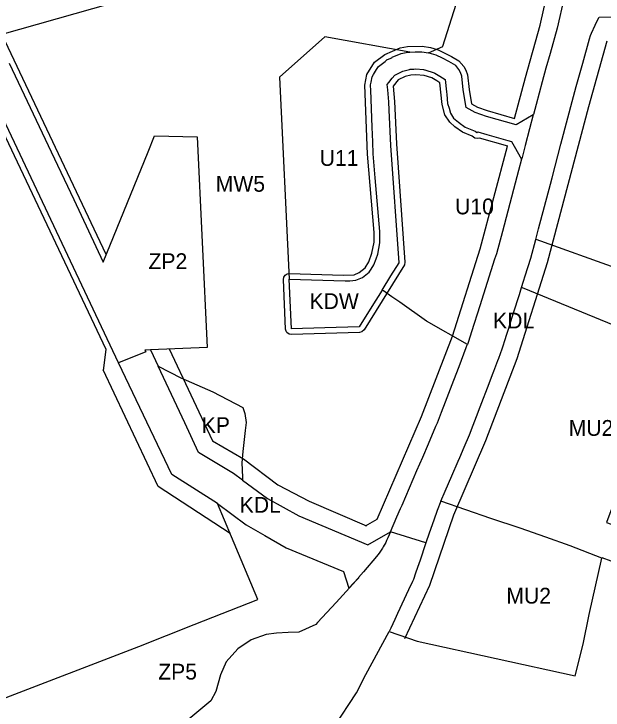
# Model space of a CAD drawing. Extents: x 7428080 to 7432143, y 5545880 to 5549217.
# Drawn here: x 7429133.6 to 7429340.3, y 5548240.2 to 5548484.5 of the extents above; entities that cross this region are included whole.
import ezdxf

# ---------------------------------------------------------------- set-up
doc = ezdxf.new("R2010")
doc.units = 0
for name, color, linetype in [('CZ_L_linie rozgraniczające tereny o różnym przeznaczeniu oraz różnych warunkach ich zabudowy i zagospodarowania', 7, 'Continuous'), ('CZ_L_maksymalne nieprzekraczalne linie zabudowy', 7, 'Continuous'), ('CZ_L_opisy_linie rozgraniczające tereny o różnym przeznaczeniu oraz różnych warunkach ich zabudowy i zagospodarowania', 7, 'Continuous')]:
    doc.layers.add(name, color=color, linetype=linetype)

msp = doc.modelspace()

# ---------------------------------------------------------------- linework, layer by layer
at = {"layer": 'CZ_L_linie rozgraniczające tereny o różnym przeznaczeniu oraz różnych warunkach ich zabudowy i zagospodarowania'}
for p, q in [((7429327.04, 5548492.22), (7429324.23, 5548479.58)), ((7429284.06, 5548473.2), (7429288.76, 5548487.94)), ((7429337.57, 5548480.59), (7429338.47, 5548482.58)), ((7429338.47, 5548482.58), (7429338.93, 5548483.39)), ((7429338.93, 5548483.39), (7429344.19, 5548483.46)), ((7429324.23, 5548479.58), (7429321.74, 5548470.69)), ((7429336.32, 5548477.77), (7429337.57, 5548480.59)), ((7429335.95, 5548476.94), (7429336.32, 5548477.77)), ((7429242.67, 5548476.47), (7429226.73, 5548462.3)), ((7429272.53, 5548471.15), (7429242.67, 5548476.47)), ((7429333.23, 5548467.22), (7429335.62, 5548475.77)), ((7429335.62, 5548475.77), (7429335.95, 5548476.94)), ((7429279.05, 5548470.85), (7429284.05, 5548473.14)), ((7429284.05, 5548473.14), (7429284.06, 5548473.2)), ((7429266.36, 5548469.34), (7429269.48, 5548470.67)), ((7429269.48, 5548470.67), (7429271.85, 5548471.11)), ((7429271.85, 5548471.11), (7429272.53, 5548471.15)), ((7429272.53, 5548471.15), (7429274.44, 5548471.26)), ((7429274.44, 5548471.26), (7429276.78, 5548471.26)), ((7429276.78, 5548471.26), (7429279.05, 5548470.85)), ((7429279.32, 5548470.8), (7429279.05, 5548470.85)), ((7429281.81, 5548470.09), (7429279.32, 5548470.8)), ((7429284.03, 5548468.98), (7429281.81, 5548470.09)), ((7429321.74, 5548470.69), (7429320.3, 5548465.51)), ((7429131.92, 5548467.27), (7429143.51, 5548442.76)), ((7429261.47, 5548466.08), (7429263.81, 5548467.86)), ((7429263.81, 5548467.86), (7429264.62, 5548468.48)), ((7429264.62, 5548468.48), (7429264.71, 5548468.55)), ((7429264.71, 5548468.55), (7429266.26, 5548469.1)), ((7429266.26, 5548469.1), (7429266.36, 5548469.34)), ((7429286.2, 5548467.83), (7429284.03, 5548468.98)), ((7429288.7, 5548466.37), (7429286.2, 5548467.83)), ((7429170.34, 5548362.1), (7429120.73, 5548466.86)), ((7429259.76, 5548463.31), (7429260.78, 5548464.97)), ((7429260.78, 5548464.97), (7429261.47, 5548466.08)), ((7429270.1, 5548464.43), (7429272.41, 5548465.06)), ((7429272.41, 5548465.06), (7429272.61, 5548465.08)), ((7429272.61, 5548465.08), (7429273.94, 5548465.17)), ((7429273.94, 5548465.17), (7429274.59, 5548465.21)), ((7429274.59, 5548465.21), (7429277.29, 5548464.98)), ((7429277.29, 5548464.98), (7429277.7, 5548464.94)), ((7429277.7, 5548464.94), (7429277.83, 5548464.93)), ((7429277.83, 5548464.93), (7429281.02, 5548463.89)), ((7429289.73, 5548465.04), (7429288.7, 5548466.37)), ((7429290.35, 5548464), (7429289.73, 5548465.04)), ((7429320.3, 5548465.51), (7429318.94, 5548460.65)), ((7429330.95, 5548459.05), (7429333.23, 5548467.22)), ((7429258.91, 5548460.56), (7429259.25, 5548462.49)), ((7429259.25, 5548462.49), (7429259.76, 5548463.31)), ((7429266.27, 5548462), (7429267.3, 5548463.08)), ((7429267.3, 5548463.08), (7429270.1, 5548464.43)), ((7429281.02, 5548463.89), (7429281.29, 5548463.74)), ((7429281.29, 5548463.74), (7429283.07, 5548462.73)), ((7429283.07, 5548462.73), (7429284.92, 5548461.52)), ((7429290.8, 5548462.65), (7429290.35, 5548464)), ((7429291.29, 5548457.88), (7429290.8, 5548462.65)), ((7429226.73, 5548462.3), (7429230.14, 5548391.41)), ((7429258.75, 5548459.65), (7429258.91, 5548460.56)), ((7429264.61, 5548459.71), (7429265.18, 5548460.49)), ((7429265.18, 5548460.49), (7429266.27, 5548462)), ((7429284.92, 5548461.52), (7429285.37, 5548457.16)), ((7429318.94, 5548460.65), (7429316.82, 5548452.76)), ((7429258.71, 5548459.44), (7429258.75, 5548459.65)), ((7429258.78, 5548457.8), (7429258.71, 5548459.44)), ((7429259.26, 5548444.81), (7429258.78, 5548457.8)), ((7429264.83, 5548457.88), (7429264.61, 5548459.71)), ((7429265.19, 5548453.7), (7429264.83, 5548457.88)), ((7429292.32, 5548451.68), (7429291.29, 5548457.88)), ((7429329.96, 5548455.51), (7429330.95, 5548459.05)), ((7429285.37, 5548457.16), (7429285.46, 5548456.29)), ((7429285.46, 5548456.29), (7429285.79, 5548453.09)), ((7429325.56, 5548438.86), (7429329.96, 5548455.51)), ((7429265.33, 5548450.72), (7429265.19, 5548453.7)), ((7429285.79, 5548453.09), (7429286.27, 5548451.45)), ((7429316.82, 5548452.76), (7429315.88, 5548449.21)), ((7429265.91, 5548438.4), (7429265.33, 5548450.72)), ((7429286.27, 5548451.45), (7429286.78, 5548449.71)), ((7429295.41, 5548449.95), (7429292.32, 5548451.68)), ((7429286.78, 5548449.71), (7429287.89, 5548447.96)), ((7429287.89, 5548447.96), (7429289.61, 5548446.5)), ((7429299.47, 5548448.55), (7429295.41, 5548449.95)), ((7429309.8, 5548445.6), (7429299.47, 5548448.55)), ((7429315.85, 5548449.08), (7429309.8, 5548445.6)), ((7429315.85, 5548449.08), (7429314.57, 5548444.24)), ((7429315.88, 5548449.21), (7429315.85, 5548449.08)), ((7429289.61, 5548446.5), (7429290.65, 5548445.75)), ((7429290.65, 5548445.75), (7429291.04, 5548445.47)), ((7429291.04, 5548445.47), (7429291.99, 5548444.79)), ((7429259.49, 5548439.66), (7429259.26, 5548444.81)), ((7429291.99, 5548444.79), (7429295.5, 5548443.33)), ((7429295.5, 5548443.33), (7429295.92, 5548443)), ((7429295.92, 5548443), (7429296.19, 5548442.79)), ((7429296.19, 5548442.79), (7429296.32, 5548443.04)), ((7429296.32, 5548443.04), (7429296.36, 5548443.12)), ((7429296.36, 5548443.12), (7429299.6, 5548442.24)), ((7429314.57, 5548444.24), (7429313, 5548438.29)), ((7429143.51, 5548442.76), (7429146.68, 5548436.06)), ((7429180.67, 5548436.17), (7429182.91, 5548441.72)), ((7429182.91, 5548441.72), (7429197.91, 5548441.33)), ((7429197.91, 5548441.33), (7429201.43, 5548367.39)), ((7429299.6, 5548442.24), (7429306.91, 5548440.13)), ((7429259.69, 5548435.44), (7429259.49, 5548439.66)), ((7429268.79, 5548397.21), (7429265.91, 5548438.4)), ((7429306.91, 5548440.13), (7429308.25, 5548439.74)), ((7429308.25, 5548439.74), (7429309.18, 5548438.09)), ((7429309.18, 5548438.09), (7429311.73, 5548433.51)), ((7429313, 5548438.29), (7429311.89, 5548434.1)), ((7429322.42, 5548426.98), (7429325.56, 5548438.86)), ((7429146.68, 5548436.06), (7429154.57, 5548419.39)), ((7429164.96, 5548397.41), (7429180.67, 5548436.17)), ((7429260.39, 5548427.04), (7429259.69, 5548435.44)), ((7429311.73, 5548433.51), (7429310.69, 5548429.58)), ((7429311.89, 5548434.1), (7429311.73, 5548433.51)), ((7429310.69, 5548429.58), (7429309.5, 5548425.07)), ((7429261.96, 5548408.13), (7429260.39, 5548427.04)), ((7429321.84, 5548424.8), (7429322.42, 5548426.98)), ((7429309.5, 5548425.07), (7429305.04, 5548408.18)), ((7429317.69, 5548409.08), (7429321.84, 5548424.8)), ((7429154.57, 5548419.39), (7429164.96, 5548397.41)), ((7429316.7, 5548405.36), (7429317.69, 5548409.08)), ((7429262.01, 5548404.13), (7429261.96, 5548408.13)), ((7429305.04, 5548408.18), (7429302.91, 5548400.33)), ((7429261.26, 5548400.2), (7429262.01, 5548404.13)), ((7429314.98, 5548398.84), (7429316.7, 5548405.36)), ((7429316.88, 5548405.29), (7429316.7, 5548405.36)), ((7429373.74, 5548384.85), (7429316.88, 5548405.29)), ((7429260.69, 5548398.57), (7429261.26, 5548400.2)), ((7429302.91, 5548400.33), (7429302.29, 5548398.4)), ((7429313.05, 5548392.63), (7429314.98, 5548398.84)), ((7429258.95, 5548394.9), (7429259.94, 5548396.41)), ((7429259.94, 5548396.41), (7429260.69, 5548398.57)), ((7429265.89, 5548392.55), (7429268.79, 5548397.21)), ((7429302.29, 5548398.4), (7429297.12, 5548382.09)), ((7429258.29, 5548393.89), (7429258.95, 5548394.9)), ((7429253.56, 5548391.02), (7429255.9, 5548392.06)), ((7429255.9, 5548392.06), (7429258.29, 5548393.89)), ((7429262.81, 5548387.59), (7429265.89, 5548392.55)), ((7429312.46, 5548390.75), (7429313.05, 5548392.63)), ((7429230.14, 5548391.37), (7429230.14, 5548391.41)), ((7429230.14, 5548391.41), (7429249.81, 5548390.78)), ((7429230.94, 5548374.03), (7429230.14, 5548391.37)), ((7429249.81, 5548390.78), (7429251.51, 5548390.89)), ((7429251.51, 5548390.89), (7429253.56, 5548391.02)), ((7429311.75, 5548388.53), (7429312.46, 5548390.75)), ((7429262.81, 5548387.59), (7429259.24, 5548381.85)), ((7429263.23, 5548387.29), (7429262.81, 5548387.59)), ((7429266.19, 5548385.23), (7429263.23, 5548387.29)), ((7429310.98, 5548386.09), (7429311.75, 5548388.53)), ((7429268.98, 5548383.3), (7429266.19, 5548385.23)), ((7429308.92, 5548379.6), (7429310.98, 5548386.09)), ((7429259.24, 5548381.85), (7429254.8, 5548374.71)), ((7429278.43, 5548376.72), (7429268.98, 5548383.3)), ((7429297.12, 5548382.09), (7429294.21, 5548372.93)), ((7429307.11, 5548373.88), (7429308.92, 5548379.6)), ((7429254.76, 5548374.65), (7429242.74, 5548374.29)), ((7429254.8, 5548374.71), (7429254.76, 5548374.65)), ((7429292.73, 5548368.45), (7429278.43, 5548376.72)), ((7429230.95, 5548373.94), (7429230.94, 5548374.03)), ((7429242.74, 5548374.29), (7429230.95, 5548373.94)), ((7429294.21, 5548372.93), (7429293.12, 5548369.48)), ((7429306.16, 5548371), (7429307.11, 5548373.88)), ((7429293.12, 5548369.48), (7429292.73, 5548368.45)), ((7429304.91, 5548366.96), (7429306.18, 5548370.99)), ((7429306.18, 5548370.99), (7429306.16, 5548371)), ((7429201.43, 5548367.39), (7429181.52, 5548366.62)), ((7429289.8, 5548360.81), (7429292.34, 5548367.43)), ((7429292.34, 5548367.43), (7429292.7, 5548368.39)), ((7429292.7, 5548368.39), (7429292.73, 5548368.45)), ((7429179.88, 5548365.87), (7429170.34, 5548362.1)), ((7429181.52, 5548366.62), (7429179.56, 5548366.55)), ((7429179.56, 5548366.55), (7429179.88, 5548365.87)), ((7429181.52, 5548366.62), (7429184.19, 5548360.91)), ((7429303.74, 5548363.7), (7429304.39, 5548365.34)), ((7429304.39, 5548365.34), (7429304.91, 5548366.96)), ((7429302.02, 5548359.16), (7429303.43, 5548362.83)), ((7429303.43, 5548362.83), (7429303.45, 5548362.83)), ((7429303.45, 5548362.83), (7429303.74, 5548363.7)), ((7429188.95, 5548322.79), (7429170.34, 5548362.1)), ((7429193.53, 5548340.93), (7429184.19, 5548360.91)), ((7429184.19, 5548360.91), (7429192.19, 5548356.8)), ((7429287.95, 5548355.97), (7429289.8, 5548360.81)), ((7429300.37, 5548354.85), (7429301.55, 5548357.93)), ((7429301.55, 5548357.93), (7429302.02, 5548359.16)), ((7429192.19, 5548356.8), (7429203.4, 5548351.91)), ((7429285.04, 5548348.39), (7429287.95, 5548355.97)), ((7429297.23, 5548346.65), (7429300.37, 5548354.85)), ((7429203.4, 5548351.91), (7429213.93, 5548346.41)), ((7429283.58, 5548344.7), (7429285.04, 5548348.39)), ((7429213.93, 5548346.41), (7429214.66, 5548344.23)), ((7429295.9, 5548343.19), (7429297.23, 5548346.65)), ((7429214.66, 5548344.23), (7429215.06, 5548341.16)), ((7429282.22, 5548341.02), (7429283.58, 5548344.7)), ((7429294.72, 5548340.11), (7429295.9, 5548343.19)), ((7429198.42, 5548330.59), (7429193.53, 5548340.93)), ((7429215.06, 5548341.16), (7429214.74, 5548338.24)), ((7429281.7, 5548339.8), (7429282.22, 5548341.02)), ((7429214.74, 5548338.24), (7429213.93, 5548330.96)), ((7429279.04, 5548333.63), (7429281.7, 5548339.8)), ((7429293.46, 5548336.83), (7429294.72, 5548340.11)), ((7429291.61, 5548332.49), (7429293.46, 5548336.83)), ((7429277.03, 5548328.97), (7429279.04, 5548333.63)), ((7429210.7, 5548323.15), (7429198.42, 5548330.59)), ((7429213.93, 5548330.96), (7429213.6, 5548326.9)), ((7429290.04, 5548328.84), (7429291.61, 5548332.49)), ((7429275, 5548324.26), (7429277.03, 5548328.97)), ((7429289.48, 5548327.53), (7429290.04, 5548328.84)), ((7429213.6, 5548326.9), (7429213.83, 5548321.88)), ((7429287.24, 5548322.33), (7429289.48, 5548327.53)), ((7429213.78, 5548320.89), (7429210.7, 5548323.15)), ((7429269.79, 5548312.14), (7429275, 5548324.26)), ((7429205.02, 5548312.72), (7429188.95, 5548322.79)), ((7429213.83, 5548321.88), (7429213.78, 5548320.89)), ((7429213.78, 5548320.89), (7429222.6, 5548314.4)), ((7429284.94, 5548316.99), (7429287.24, 5548322.33)), ((7429283.45, 5548313.44), (7429284.94, 5548316.99)), ((7429222.6, 5548314.4), (7429233.58, 5548308.32)), ((7429283.45, 5548313.44), (7429282.1, 5548310.25)), ((7429300.98, 5548307.36), (7429283.45, 5548313.44)), ((7429209.95, 5548300.95), (7429205.02, 5548312.72)), ((7429205.02, 5548312.72), (7429215.04, 5548305.17)), ((7429268.01, 5548308.02), (7429269.28, 5548310.97)), ((7429269.28, 5548310.97), (7429269.79, 5548312.14)), ((7429282.1, 5548310.25), (7429280.92, 5548306.79)), ((7429233.58, 5548308.32), (7429257.79, 5548298.16)), ((7429265.71, 5548302.68), (7429268.01, 5548308.02)), ((7429280.92, 5548306.79), (7429279.36, 5548302.24)), ((7429311.27, 5548303.99), (7429300.98, 5548307.36)), ((7429215.04, 5548305.17), (7429221.69, 5548301.41)), ((7429320.2, 5548300.85), (7429311.27, 5548303.99)), ((7429221.69, 5548301.41), (7429229.11, 5548297.07)), ((7429257.79, 5548298.16), (7429265.71, 5548302.68)), ((7429265.71, 5548302.68), (7429264.81, 5548300.58)), ((7429278.18, 5548298.81), (7429265.71, 5548302.68)), ((7429279.36, 5548302.24), (7429278.18, 5548298.81)), ((7429219.15, 5548278.95), (7429209.95, 5548300.95)), ((7429264.06, 5548299), (7429263.18, 5548297.45)), ((7429264.38, 5548299.67), (7429264.06, 5548299)), ((7429264.81, 5548300.58), (7429264.38, 5548299.67)), ((7429278.18, 5548298.81), (7429276.01, 5548292.48)), ((7429328.77, 5548297.85), (7429320.2, 5548300.85)), ((7429229.11, 5548297.07), (7429249.29, 5548288.8)), ((7429262.93, 5548297), (7429261.79, 5548295.18)), ((7429263.16, 5548297.42), (7429262.93, 5548297)), ((7429263.18, 5548297.45), (7429263.16, 5548297.42)), ((7429339.94, 5548293.49), (7429328.77, 5548297.85)), ((7429260.87, 5548294.09), (7429256.3, 5548288.71)), ((7429261.79, 5548295.18), (7429260.87, 5548294.09)), ((7429275.8, 5548291.87), (7429274.55, 5548288.21)), ((7429276.01, 5548292.48), (7429275.8, 5548291.87)), ((7429335.47, 5548273.67), (7429339.93, 5548293.42)), ((7429339.93, 5548293.42), (7429339.94, 5548293.49)), ((7429249.29, 5548288.8), (7429249.28, 5548288.79)), ((7429249.28, 5548288.79), (7429251.17, 5548282.96)), ((7429251.17, 5548282.96), (7429254.47, 5548286.56)), ((7429254.46, 5548286.46), (7429253.66, 5548285.6)), ((7429254.47, 5548286.56), (7429254.46, 5548286.46)), ((7429254.54, 5548286.65), (7429254.47, 5548286.56)), ((7429256.3, 5548288.71), (7429254.54, 5548286.65)), ((7429274.55, 5548288.21), (7429273.79, 5548285.99)), ((7429253.66, 5548285.6), (7429246.64, 5548277.96)), ((7429273.44, 5548285.25), (7429272.08, 5548282.34)), ((7429273.79, 5548285.99), (7429273.44, 5548285.25)), ((7429272.08, 5548282.34), (7429268.23, 5548274.09)), ((7429196.87, 5548270.18), (7429219.15, 5548278.95)), ((7429246.64, 5548277.96), (7429240.18, 5548270.95)), ((7429267.23, 5548271.95), (7429265.83, 5548268.95)), ((7429268.23, 5548274.09), (7429267.23, 5548271.95)), ((7429333.33, 5548263.33), (7429335.47, 5548273.67)), ((7429177.42, 5548262.52), (7429196.87, 5548270.18)), ((7429239.53, 5548270.24), (7429233.62, 5548267.48)), ((7429240.18, 5548270.95), (7429239.53, 5548270.24)), ((7429225.79, 5548267.17), (7429222.05, 5548266.67)), ((7429229.87, 5548267.33), (7429225.79, 5548267.17)), ((7429233.62, 5548267.48), (7429229.87, 5548267.33)), ((7429257.04, 5548252.68), (7429265.27, 5548267.75)), ((7429265.83, 5548268.95), (7429265.27, 5548267.75)), ((7429265.27, 5548267.75), (7429275.08, 5548264.33)), ((7429216.84, 5548264.76), (7429212.19, 5548261.67)), ((7429222.05, 5548266.67), (7429216.84, 5548264.76)), ((7429124.64, 5548242.13), (7429177.42, 5548262.52)), ((7429275.08, 5548264.33), (7429330.57, 5548252.2)), ((7429330.57, 5548252.2), (7429333.33, 5548263.33)), ((7429212.19, 5548261.67), (7429208.11, 5548257.07)), ((7429208.11, 5548257.07), (7429206.08, 5548252.55)), ((7429206.08, 5548252.55), (7429204.44, 5548246.68)), ((7429253.81, 5548246.23), (7429257.04, 5548252.68)), ((7429204.44, 5548246.68), (7429202.7, 5548243.37)), ((7429240.31, 5548225.7), (7429253.81, 5548246.23)), ((7429202.7, 5548243.37), (7429192.13, 5548234.58))]:
    msp.add_line(p, q, dxfattribs=at)
for points in [[(7429311.75, 5548388.53), (7429311.92, 5548388.46), (7429364.74, 5548366.81), (7429364.8, 5548366.69)], [(7429364.8, 5548366.68), (7429364.56, 5548366.78), (7429353.17, 5548336.76), (7429353.18, 5548336.53), (7429353.02, 5548336.6), (7429347.38, 5548321.65), (7429344.45, 5548313.86), (7429341.48, 5548305.99), (7429347.09, 5548303.97), (7429347.05, 5548303.86), (7429347.01, 5548303.73), (7429343.2, 5548292.46), (7429343.19, 5548292.43), (7429343.19, 5548292.42), (7429343.19, 5548292.42), (7429339.97, 5548293.62), (7429339.94, 5548293.49)]]:
    msp.add_lwpolyline(points, dxfattribs=at)
at = {"layer": 'CZ_L_maksymalne nieprzekraczalne linie zabudowy'}
for points in [[(7429231.04, 5548506.18), (7429129.39, 5548477.29), (7429165.81, 5548400.16)], [(7429306.91, 5548438.05), (7429296.92, 5548440.9), (7429296.13, 5548440.79), (7429295.38, 5548440.96), (7429294.35, 5548441.64), (7429290.95, 5548443.08), (7429288.35, 5548444.94), (7429286.53, 5548446.5), (7429284.86, 5548449.13), (7429283.82, 5548452.75), (7429283.02, 5548460.37), (7429282.04, 5548461.01), (7429280.24, 5548462.04), (7429277.5, 5548462.94), (7429274.67, 5548463.2), (7429272.82, 5548463.09), (7429270.9, 5548462.58), (7429268.47, 5548461.41), (7429266.69, 5548459.14), (7429267.19, 5548453.8), (7429267.89, 5548438.9), (7429270.79, 5548397.35), (7429270.62, 5548396.4), (7429256.45, 5548373.59), (7429255.72, 5548372.89), (7429254.84, 5548372.65), (7429231.01, 5548371.94), (7429230.13, 5548372.12), (7429229.41, 5548372.66), (7429229.08, 5548373.22), (7429228.95, 5548373.83), (7429228.14, 5548391.33), (7429228.26, 5548392.11), (7429228.76, 5548392.86), (7429229.42, 5548393.28), (7429230.18, 5548393.41), (7429249.21, 5548392.8), (7429252.96, 5548392.98), (7429254.79, 5548393.76), (7429256.87, 5548395.37), (7429258.18, 5548397.45), (7429259.24, 5548400.5), (7429260, 5548404.42), (7429259.97, 5548407.75), (7429257.69, 5548435.32), (7429256.71, 5548459.49), (7429257.42, 5548463.3), (7429260.1, 5548467.54), (7429263.76, 5548470.31), (7429269.11, 5548472.63), (7429271.72, 5548473.11), (7429276.84, 5548473.26), (7429279.75, 5548472.75), (7429282.51, 5548471.97), (7429287.14, 5548469.59), (7429289.77, 5548468.05), (7429291.44, 5548466.08), (7429292.17, 5548464.84), (7429292.74, 5548463.11), (7429293.29, 5548458.01), (7429294.18, 5548452.93), (7429296.29, 5548451.76), (7429299.72, 5548450.58), (7429309.31, 5548447.82), (7429313.14, 5548462.2), (7429318.29, 5548480.63), (7429320.87, 5548492.11)], [(7429341.66, 5548475.02), (7429335.21, 5548451.88), (7429320.74, 5548397.16), (7429310.09, 5548363.49), (7429299.06, 5548334.66), (7429287.9, 5548308.54), (7429279.42, 5548283.92), (7429270.71, 5548265.21)], [(7429164.99, 5548359.38), (7429165.92, 5548366.77), (7429115.06, 5548474.08)], [(7429256.94, 5548304.79), (7429261.11, 5548307.17), (7429276.65, 5548343.25), (7429287.45, 5548371.46), (7429297.15, 5548402.02), (7429306.74, 5548438.09)], [(7429188.05, 5548366.97), (7429203.23, 5548334.65), (7429214.2, 5548328.32), (7429226.21, 5548319.22), (7429237.2, 5548313.54), (7429257.31, 5548304.81)], [(7429209.43, 5548302.18), (7429184.26, 5548318.69), (7429164.92, 5548359.54)]]:
    msp.add_lwpolyline(points, dxfattribs=at)

# ---------------------------------------------------------------- texts
at = {"layer": 'CZ_L_opisy_linie rozgraniczające tereny o różnym przeznaczeniu oraz różnych warunkach ich zabudowy i zagospodarowania'}
for s, p in [('U11', (7429240.89, 5548431.19)), ('MW5', (7429204.4, 5548422.1)), ('U10', (7429288.42, 5548414.18)), ('ZP2', (7429180.81, 5548394.95)), ('KDW', (7429237.31, 5548380.94)), ('KDL', (7429301.74, 5548374.11)), ('KP', (7429199.49, 5548337.41)), ('MU24', (7429328.28, 5548336.42)), ('KDL', (7429212.83, 5548309.43)), ('MU2', (7429306.4, 5548277.53)), ('ZP5', (7429184.22, 5548250.86))]:
    msp.add_text(s, height=5.549, dxfattribs=at).set_placement(p)

doc.saveas('drawing.dxf')
